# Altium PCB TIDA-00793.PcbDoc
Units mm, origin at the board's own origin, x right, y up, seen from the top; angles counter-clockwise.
Board outline 22.86 x 22.86 mm, 2 copper layers (Top Layer, Bottom Layer), stack 1.575 mm thick; 34 components, 19 nets, 97 pads, 13 vias.
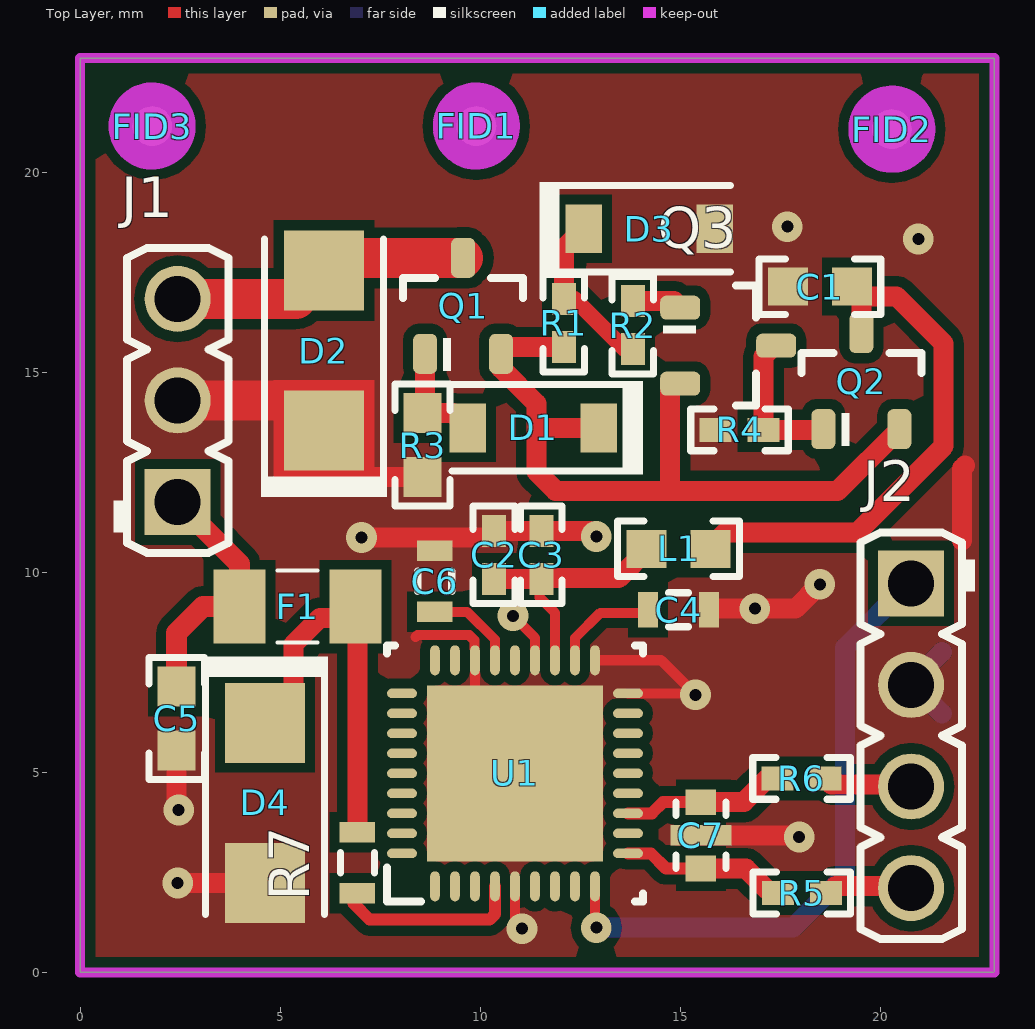
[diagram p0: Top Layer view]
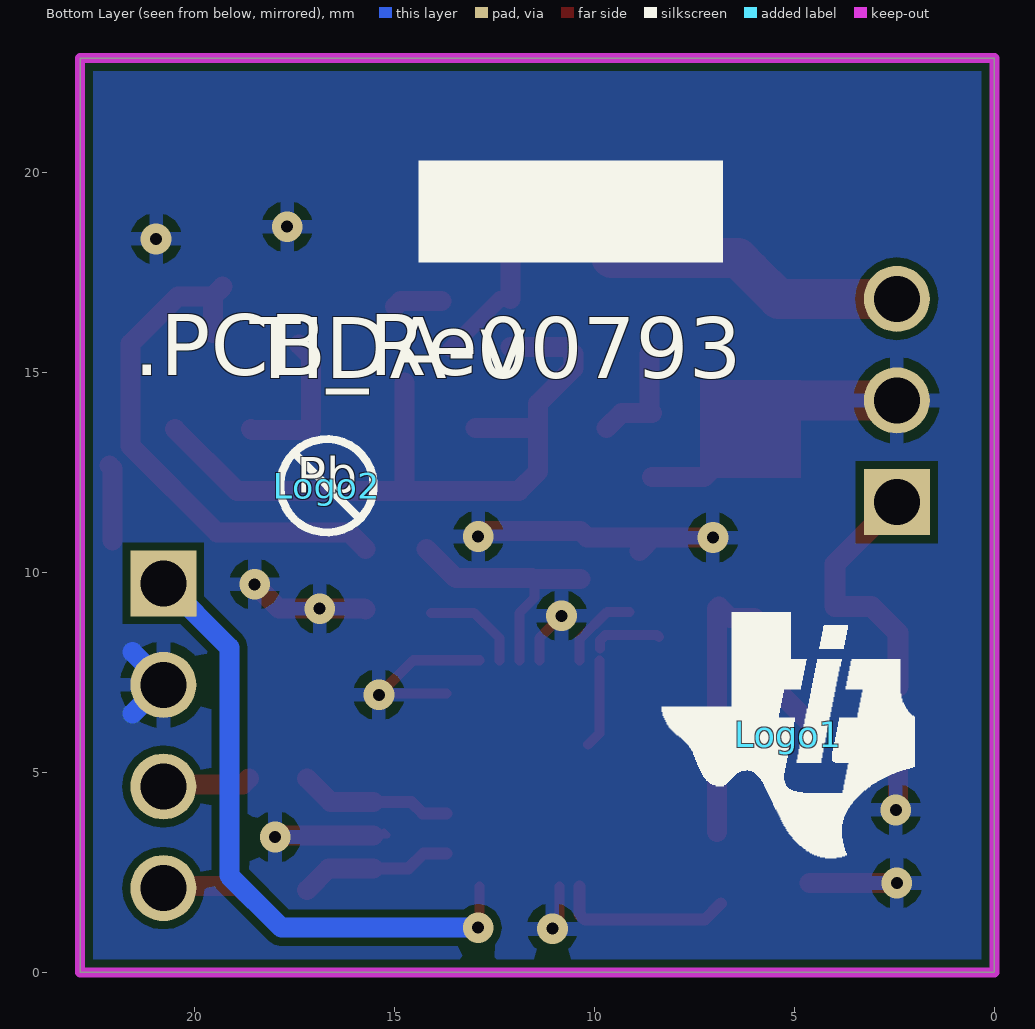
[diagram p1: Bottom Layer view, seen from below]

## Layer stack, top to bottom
Top Solder: solder mask 0.0102, Solder Resist, Dk 3.5
Top Layer: signal copper 0.0356
Dielectric1: core 1.5037, FR-4, Dk 4.8
Bottom Layer: signal copper 0.0356
Bottom Solder: solder mask 0.0102, Solder Resist, Dk 3.5

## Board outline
0,0 22.86,0 22.86,22.86 0,22.86

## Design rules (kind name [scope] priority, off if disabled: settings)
AcuteAngle [All] p1: minimum=4.50000000000000E+0001 checktracksonly=FALSE
AssemblyTestPointUsage [All] p1: valid=2
Clearance Clearance_6 [InNamedPolygon('Top Layer-No Net')] p1: gap=0.254
Clearance Clearance_5 [InNamedPolygon('Bottom Layer-No Net')] p2: gap=0.2
Clearance Clearance_4 [InNamedPolygon('Top Layer-No Net 1')] p3: gap=0.2
Clearance Clearance_3 [InNamedPolygon('Top Layer-No Net 1')] p4: gap=0.254
Clearance Clearance_2 [InNamedPolygon('Top Layer-No Net 1')] p5: gap=0.1
Clearance Clearance_1 [InNamedPolygon('Top Layer-No Net 1')] p6: gap=0.154
Clearance Clearance_Keepouts [((IsTrack Or IsArc) And Not InPoly) And IsFree and IsKeepOut vs ((IsTrack Or IsArc) And Not InPoly) And IsFree and IsKeepOut] p7: gap=0
Clearance Clearance_BoardEdge_MountingHoles [OnCopper and InComponentClass('Mounting Holes') vs IsKeepOut] p8: gap=1.016
Clearance Clearance_BoardEdge_Poly [OnCopper and InPoly vs IsKeepOut] p9: gap=0.635
Clearance Clearance_BoardEdge [OnCopper and Not InComponentClass('Logo') and not InComponentClass('FiducialMark') and not InRegion(1000,500,4000,800) and Not IsKeepout vs IsKeepOut] p10: gap=0.254
Clearance Clearance_Poly [InPolygon vs IsPad] p11: gap=0.1
Clearance [All] p12: gap=0.127
ComponentClearance ComponentClearance_MountingHoles_FiducialMarks [InComponentClass('Mounting Holes') vs InComponentClass('FiducialMark')] p1: gap=1.27 collisioncheckmode=3 verticalgap=0.254 showdistances=FALSE
ComponentClearance ComponentClearance_Shunt [InComponentClass('Header') vs InComponentClass('Shunt')] p2: gap=0 collisioncheckmode=3 verticalgap=0 showdistances=FALSE
ComponentClearance ComponentClearance_Logo [InComponentClass('Logo')] p3: gap=1.27 collisioncheckmode=3 verticalgap=0.254 showdistances=FALSE
ComponentClearance ComponentClearance_ScrewToNut [(HasFootprint('NY PMS 440 0025 PH')) vs (HasFootprint('Keystone_1902C'))] p4: gap=0.127 collisioncheckmode=3 verticalgap=0.254 showdistances=FALSE
ComponentClearance ComponentClearance_MountingHoles [InComponentClass('Mounting Holes')] p5: gap=6.35 collisioncheckmode=3 verticalgap=2540 showdistances=FALSE
ComponentClearance ComponentClearance_SmallPassives [HasFootprint('0201*') or HasFootprint('0402*') or HasFootprint('0508') or HasFootprint('0603*') or HasFootprint('0612') or HasFootprint('0805*') or HasFootprint('0815*') or HasFootprint('0830*') or HasFootprint('1206*') or HasFootprint('1210*') or HasFootprint('1808*') or HasFootprint('1812*') or HasFootprint('1825*') or HasFootprint('2010*') or HasFootprint('2220*') or HasFootprint('2225*') or HasFootprint('2512*') or HasFootprint('2728*') or HasFootprint('3518*') vs HasFootprint('0201*') or HasFootprint('0402*') or HasFootprint('0508') or HasFootprint('0603*') or HasFootprint('0612') or HasFootprint('0805*') or HasFootprint('0815*') or HasFootprint('0830*') or HasFootprint('1206*') or HasFootprint('1210*') or HasFootprint('1808*') or HasFootprint('1812*') or HasFootprint('1825*') or HasFootprint('2010*') or HasFootprint('2220*') or HasFootprint('2225*') or HasFootprint('2512*') or HasFootprint('2728*') or HasFootprint('3518*')] p6: gap=0.508 collisioncheckmode=3 verticalgap=0.254 showdistances=FALSE
ComponentClearance ComponentClearance_THtoSMT [IsThruComponent vs IsSMTComponent] p7: gap=0.5 collisioncheckmode=3 verticalgap=0.762 showdistances=FALSE
ComponentClearance ComponentClearance_THtoTH [IsThruComponent vs IsThruComponent] p8: gap=3 collisioncheckmode=3 verticalgap=0.762 showdistances=FALSE
ComponentClearance [All] p9: gap=0.216 collisioncheckmode=3 verticalgap=0.254 showdistances=FALSE
DiffPairsRouting [All] p1: maxlimit=2.54 minlimit=0.254 mostfreqgap=0.254 toplayer_minwidth=0.381 toplayer_maxwidth=0.381 toplayer_prefwidth=0.381 bottomlayer_minwidth=0.381 bottomlayer_maxwidth=0.381 bottomlayer_prefwidth=0.381 maxuncoupledlength=25.4
FabricationTestPointUsage TestPointUsage [All] p1: valid=2 allowmultiple=FALSE
FabricationTestpoint Testpoint [All] p1: side=3 testpointundercomponent=TRUE minsize=1.016 maxsize=2.54 preferedsize=1.524 minholesize=0 maxholesize=1.016 preferedholesize=0.813 testpointgrid=0.025 allowsidetop=TRUE allowsidebottom=TRUE usegrid=TRUE gridtolerance=0
FanoutControl Fanout_LCC [IsLCC] p1: bgadir=Out bgaviamode=Centered fanoutstyle=Auto fanoutdirection=Alternating viagrid=0.025 // Fanout_LCC (Default Rule)
FanoutControl Fanout_BGA [IsBGA] p2: bgadir=Out bgaviamode=Centered fanoutstyle=Auto fanoutdirection=Alternating viagrid=0.025 // Fanout_BGA (Default Rule)
FanoutControl Fanout_Default [All] p4: bgadir=Out bgaviamode=Centered fanoutstyle=Auto fanoutdirection=Alternating viagrid=0.025 // Fanout_Default (Default Rule)
FanoutControl Fanout_Small [(CompPinCount < 5)] p5: bgadir=Out bgaviamode=Centered fanoutstyle=Auto fanoutdirection=OutThenIn viagrid=0.025 // Fanout_Small (Default Rule)
HoleSize [All] p1: absolutevalues=TRUE maxlimit=6.375 minlimit=0.2 maxpercent=80.000 minpercent=20.000
MinimumAnnularRing MinimumAnnularRing_ThermalPadVias [IsVia and InAnyComponent] p1: minimumring=0.15
MinimumAnnularRing [All] p2: minimumring=0.229
MinimumSolderMaskSliver MinimumSolderMaskSliver_Logo [InComponentClass('Logo') vs InComponentClass('Logo')] p1: minsoldermaskwidth=0.018
MinimumSolderMaskSliver [All] p2: minsoldermaskwidth=0.01
PlaneClearance [All] p1: clearance=0.308
PlaneConnect [All] p1: planeconnectstyle=Relief reliefexpansion=0.254 reliefentries=4 reliefconductorwidth=0.254 reliefairgap=0.154
PolygonConnect PolygonConnect_3 [All vs IsNamedPolygon('Bottom Layer-No Net')] p1: connectstyle=Relief reliefconductorwidth=0.354 reliefentries=4 polygonreliefangle="90 Angle" airgapwidth=0.254
PolygonConnect PolygonConnect_2 [All vs IsNamedPolygon('Bottom Layer-No Net')] p2: connectstyle=Relief reliefconductorwidth=0.354 reliefentries=4 polygonreliefangle="90 Angle" airgapwidth=0.254
PolygonConnect PolygonConnect_1 [All vs IsNamedPolygon('Top Layer-No Net')] p3: connectstyle=Direct reliefconductorwidth=0.254 reliefentries=4 polygonreliefangle="90 Angle" airgapwidth=0.254
PolygonConnect [All] p4: connectstyle=Relief reliefconductorwidth=0.354 reliefentries=4 polygonreliefangle="90 Angle" airgapwidth=0.254
RoutingVias ThermalPadVias [IsVia and InAnyComponent] p1: holewidth=0.2 width=0.5 viastyle="Through Hole" minholewidth=0.2 minwidth=0.5 maxholewidth=0.33 maxwidth=0.6
RoutingVias [All] p2: holewidth=0.406 width=0.864 viastyle="Through Hole" minholewidth=0.2 minwidth=0.66 maxholewidth=1.016 maxwidth=1.651
SilkToBoardRegionClearance [Not ((IsComment or IsDesignator) And (Hide <> 'False')) and not InRegion(1000,500,4000,800)] p1:
SilkToSilkClearance SilkToSilkClearance_Pb-FreeLogo [(HasFootprint('Pb-Free_Overlay_Medium') OR HasFootprint('Pb-Free_Overlay_Small')) vs (HasFootprint('Pb-Free_Overlay_Medium') OR HasFootprint('Pb-Free_Overlay_Small'))] p1: silktosilkclearance=0
SilkToSilkClearance [All] p2: silktosilkclearance=0
SilkToSolderMaskClearance SilkToComonentPadClearance [IsPad and InAnycomponent] p1: minsilkscreentomaskgap=0 clearancetoexposedcopper=TRUE
SilkToSolderMaskClearance "Silk to Solder Mask Opening" [All] p2 off: minsilkscreentomaskgap=0 clearancetoexposedcopper=FALSE
SolderMaskExpansion [All] p1: expansion=0.05
UnpouredPolygon [All] p1: allowunpoured=FALSE
Width [All] p1: maxlimit=2.54 minlimit=0.152 preferedwidth=0.254 checkconnectedcopper=TRUE
13 further rules are at their usual default settings.

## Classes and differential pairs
component class Header: J1 J2
component class Logo: Logo1
component class TIDA-00793_Hardware: FID1 FID2 FID3 Logo1 Logo2 ZZ1 ZZ2 ZZ3
component class FiducialMark: FID1 FID2 FID3
component class AssemblyNote: ZZ1 ZZ2 ZZ3
component class TIDA-00793_PressureSensorSchematic: C1 C2 C3 C4 C5 C6 C7 D1 D2 D3 D4 F1 J1 J2 L1 PGA301 Q1 Q2 Q3 R1 R2 R3 R4 R5 R6 R7 U1

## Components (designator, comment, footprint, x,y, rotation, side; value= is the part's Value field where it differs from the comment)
C1 "GRM188Z71C225KE43" 0603 18.494,17.145 r180 top
C2 "GRM155R71C153JA01D" 0402 10.349,10.439 r90 top
C3 "GRM155R71C104JA88D" 0402 11.532,10.439 r90 top
C4 "0603YC104JAT2A" 0603S 14.963,9.068 r180 top
C5 "C0603C680J5GACTU" 0603 2.416,6.35 r270 top
C6 "0603YC104JAT2A" 0603S 8.867,9.779 r270 top
C7 "500X14W103MV4T" X2Y_0603 15.522,3.429 r270 top
D1 "MMSZ5232B-7-F" SOD-123 11.331,13.614 r180 top
D2 "SM4T23CAY" SMA 6.099,15.545 r90 top
D3 "MMSZ5232B-7-F" SOD-123 14.227,18.593 r0 top
D4 "1SMA5922BT3G" SMA 4.625,4.242 r270 top
F1 "NANOSMDC020F-2" FUSE_NANO02 5.438,9.144 r0 top
FID1 "Fiducial" Fiducial10-20 9.906,21.158 r0 top
FID2 "Fiducial" Fiducial10-20 20.295,21.082 r0 top
FID3 "Fiducial" Fiducial10-20 1.803,21.158 r0 top
J1 "61300311121" WURTH_61300311121 2.441,14.3 r90 top
J2 "61300411121" WURTH_61300411121 20.777,5.918 r270 top
L1 "74279266" 0603 14.963,10.592 r180 top
Logo1 "Texas Instruments" TI_Symbol_Overlay_Medium 5.156,5.944 r180 bottom
Logo2 "Pb-Free Symbol" Pb-Free_Overlay_Small 16.688,12.167 r180 bottom
Q1 "DMP3098L-7" SOT-23 9.578,16.662 r90 top
Q2 "FMMT720TA" SOT-23 19.535,14.783 r90 top
Q3 "BC857C-7-F" SOT-23 16.205,15.672 r0 top
R1 "CRCW04022K74FKED" 0402 12.093,16.231 r270 top
R2 "CRCW04026K81FKED" 0402 13.82,16.18 r90 top
R3 "CRCW060320K0FKEA" 0603 8.562,13.183 r90 top
R4 "CRCW04026K81FKED" 0402 16.487,13.564 r0 top
R5 "CRCW040249R9FKED" 0402 18.045,1.986 r180 top
R6 "CRCW040249R9FKED" 0402 18.037,4.851 r180 top
R7 "MCR03EZPJ000" 0603S 6.934,2.743 r90 top
U1 "PGA301RHHQ1" RHH0036C_NV 10.874,4.978 r90 top
ZZ1 "These assemblies are ESD sensitive, ESD precautions shall be observed." AssemblyNote 3.251,37.29 r0 top
ZZ2 "These assemblies must be clean and free from flux and all contaminants. Use of no clean flux is not acceptable." AssemblyNote 3.251,35.041 r0 top
ZZ3 "These assemblies must comply with workmanship standards IPC-A-610 Class 2, unless otherwise specified." AssemblyNote 3.251,32.791 r0 top

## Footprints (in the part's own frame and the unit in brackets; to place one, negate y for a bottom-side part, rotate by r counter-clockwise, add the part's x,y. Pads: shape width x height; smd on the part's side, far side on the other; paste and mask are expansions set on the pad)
0402 [mm] "0402 from SM-752 data"
  rect 0.8x0.6 smd: 1(-0.6,0) 2(0.6,0)
  silkscreen extent -1.22,-0.52 1.22,0.52, body extent -0.55,-0.3 0.55,0.3, height 0.6
0603 [mm] "0603 from SM-752 data"
  rect 1x0.95 smd: 1(-0.8,0) 2(0.8,0)
  silkscreen extent -1.52,-0.69 1.52,0.69, body extent -0.87,-0.47 0.87,0.47, height 1
0603S [mil]
  rect 20x35 smd: 1(-30,0) 2(30,0)
  silkscreen extent -10,-17 10,17, body extent -34,-19 34,19, height 39
AssemblyNote [mm] "Assembly Note"
Fiducial10-20 [mm]
  round 1 smd mask+0.5: 1(0,0)
  Top Layer keep-out circle w1.178: c0,0 r0.5
FUSE_NANO02 [mm] "SMD, Body 3.2x1.585mm"
  rect 1.3x1.85 smd: 1(-1.45,0) 2(1.45,0)
  silkscreen extent -0.5,-0.9 0.5,0.9, body extent -1.7,-0.9 1.7,0.9, height 0.82
Pb-Free_Overlay_Small [mm]
  silkscreen extent -1.17,-1.17 1.16,1.17
RHH0036C_NV [mm] "QFN, 36-Leads, Body 6x6mm, Pitch 0.5mm, Thermal Pad 4.4x4.4mm, TI Recommended"
  oval 0.75x0.24 smd: 1(-2.825,2) 2(-2.825,1.5) 3(-2.825,1) 4(-2.825,0.5) 5(-2.825,0) 6(-2.825,-0.5) 7(-2.825,-1) 8(-2.825,-1.5) 9(-2.825,-2) 19(2.825,-2) 20(2.825,-1.5) 21(2.825,-1) 22(2.825,-0.5) 23(2.825,0) 24(2.825,0.5) 25(2.825,1) 26(2.825,1.5) 27(2.825,2)
  oval 0.24x0.75 smd: 10(-2,-2.825) 11(-1.5,-2.825) 12(-1,-2.825) 13(-0.5,-2.825) 14(0,-2.825) 15(0.5,-2.825) 16(1,-2.825) 17(1.5,-2.825) 18(2,-2.825) 28(2,2.825) 29(1.5,2.825) 30(1,2.825) 31(0.5,2.825) 32(0,2.825) 33(-0.5,2.825) 34(-1,2.825) 35(-1.5,2.825) 36(-2,2.825)
  rect 4.4x4.4 smd paste-2.2: 37(0,0)
  silkscreen extent -3.2,-3.2 3.2,3.2, body extent -3.05,-3.05 3.05,3.05, height 1.01
SMA [mm] "Molded Diode, 2-Leads, Body 4.3x2.6mm, IPC Medium Density, based on OnSemi component dimensions and land pattern"
  rect 2x2 smd: 1(-2,0) 2(2,0)
  silkscreen extent -3.66,-1.57 2.79,1.57, body extent -2.6,-1.3 2.6,1.3, height 2.42
SOD-123 [mm] "On Semi recommended land pattern"
  rect 0.915x1.22 smd: 1(-1.637,0) 2(1.637,0)
  silkscreen extent -2.74,-1.17 2.03,1.17, body extent -1.93,-0.9 1.93,0.9, height 1.35
SOT-23 [mm] "SOT23, 3-Leads, Body 2.9x1.3mm, Pitch 0.95mm, Lead Span 2.5mm, IPC Medium Density"
  rrect50% 1x0.6 smd: 1(-1.2,0.95) 2(-1.2,-0.95) 3(1.2,0)
  silkscreen extent -1.62,-1.5 0.7,1.5, body extent -1.16,-1.45 1.21,1.45, height 1
TI_Symbol_Overlay_Medium [mm]
  silkscreen extent -3.16,-3.09 3.16,3.06
WURTH_61300311121 [mm] "Header, 2.54mm, 3x1, TH"
  rect 1.65x1.65 hole 1.15: 1(-2.54,0)
  round 1.65 hole 1.15: 2(0,0) 3(2.54,0)
  silkscreen extent -3.81,-1.27 3.81,1.6, body extent -3.81,-1.27 3.81,1.27, height 8.54
WURTH_61300411121 [mm] "Header, 2.54mm, 4x1, TH"
  rect 1.65x1.65 hole 1.15: 1(-3.81,0)
  round 1.65 hole 1.15: 2(-1.27,0) 3(1.27,0) 4(3.81,0)
  silkscreen extent -5.08,-1.27 5.08,1.6, body extent -5.08,-1.27 5.08,1.27, height 8.54
X2Y_0603 [mm] "0402 from SM-752 data"
  rect 0.64x0.76 smd: 1(-0.83,0) 2(0.83,0)
  rect 0.51x1.52 smd: 3(0,0)
  silkscreen extent -0.82,-0.63 0.82,0.63, body extent -0.88,-0.51 0.88,0.51, height 0.75

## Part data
C1: "CAP, CERM, 2.2 µF, 16 V, +/- 10%, X7R, 0603"
C2: "CAP, CERM, 0.015 µF, 16 V, +/- 5%, X7R, 0402"
C3: "CAP, CERM, 0.1 µF, 16 V, +/- 5%, X7R, 0402"
C4 C6: "CAP, CERM, 0.1 µF, 16 V, +/- 5%, X7R, 0603"
C5: "CAP, CERM, 68 pF, 50 V, +/- 5%, C0G/NP0, 0603"
C7: "CAP, CERM, 0.01 µF, 50 V, +/- 20%, X7R, 0603"
D1 D3: "Diode, Zener, 5.6 V, 500 mW, SOD-123"
D2: library part SM4T23AY/CAY, "Diode, TVS, Bi, 20 V, 400 W, AEC-Q101, SMA"
D4: "Diode, Zener, 7.5 V, 1.5 W, AEC-Q101, SMA"
F1: "Fuse, Resettable, 0.2 A, 24 V, SMD"
FID1 FID2 FID3: "Fiducial mark.  There is nothing to buy or mount."
J1: "Header, 2.54 mm, 3x1, Gold, TH"
J2: "Header, 2.54 mm, 4x1, Gold, TH"
L1: "Ferrite Bead, 1000 ohm @ 100 MHz, 0.2 A, 0603"
Logo1: library part TI_Logo, "Texas Instrument Corporate Signature"
Logo2: library part Pb-Free
Q1: "MOSFET, P-CH, -30 V, -3.8 A, AEC-Q101, SOT-23"
Q2: library part "FMMT720TA, Diodes Inc.", "Transistor, PNP, 40 V, 1.5 A, AEC-Q101, SOT-23"
Q3: library part "BC857C-7-F, Diodes Inc.", "Transistor, PNP, 45 V, 0.1 A, SOT-23"
R1: "RES, 2.74 k, 1%, 0.063 W, 0402"
R2 R4: "RES, 6.81 k, 1%, 0.063 W, 0402"
R3: "RES, 20.0 k, 1%, 0.1 W, 0603"
R5 R6: "RES, 49.9, 1%, 0.063 W, 0402"
R7: "RES, 0, 5%, 0.1 W, 0603"
U1: "Resistive Bridge Sensor Signal Conditioner for Automotive application, RHH0036C"
ZZ1 ZZ2 ZZ3: library part AssemblyNote

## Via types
v1: diameter 0.77, hole 0.3, Top Layer to Bottom Layer, 13 vias

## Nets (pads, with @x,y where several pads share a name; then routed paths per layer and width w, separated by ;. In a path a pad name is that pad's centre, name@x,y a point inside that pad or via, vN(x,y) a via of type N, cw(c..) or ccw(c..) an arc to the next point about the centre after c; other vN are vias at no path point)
+5V: D2.2 J1.3 Q1.3 | length 7.6
  Top Layer w1: J1.3 5.394,16.84 D2.2 6.416,17.862 Q1.3
GND: C1.2 C2.2 C3.2 C4.1 C5.2 C6.1 C7.3 D2.1 D3.2 D4.2 J1.2 J2.2 R3.1 R4.1 U1.5 U1.18 U1.19 U1.22 U1.25 U1.37 | length 38.2
  Top Layer w0.156: C7.3 C7.3@15.268,3.429 ; C7.3@15.268,3.429 15.268,3.525 15.172,3.429 C7.3@15.268,3.429
  Top Layer w0.25: 8.382,8.382 8.43,8.43 9.731,8.43 9.856,8.306 U1.25@9.856,8.103 ; U1.25 9.874,5.978 U1.37@10.159,5.693 ; v1(10.823,8.915) 11.374,8.365 U1.22 ; U1.5 10.874,1.27 v1(11.052,1.092) ; U1.18 v1@15.352,6.978
  Top Layer w0.254: U1.19 14.527,7.803 v1@15.352,6.978
  Top Layer w0.5: C5.2 2.416,4.115 v1(2.466,4.064) ; v1(2.441,2.235) 4.619,2.235 D4.2 ; D2.1 7.261,12.383 R3.1 ; v1(7.038,10.871) 8.537,10.871 ; C6.1 8.537,10.871 ; v1(12.906,10.897) 12.763,11.039 11.492,11.039 C2.2 10.181,10.871 8.537,10.871 ; C7.3 17.936,3.429 v1(17.98,3.385) ; C4.1 15.751,9.093 v1(16.868,9.093) 17.884,9.093 v1(18.494,9.703) ; 22.05,10.799 22.05,12.601 22.123,12.675
  Top Layer w1: J1.2 5.343,14.3 D2.1
  Bottom Layer w0.5: 21.549,6.469 20.78,7.239 21.549,8.009
  other v1: 15.389,6.941 20.958,18.339 17.681,18.644
NetC2_1: C2.1 C3.1 L1.2 U1.21 | length 6.3
  Top Layer w0.25: C3.1@11.492,9.839 11.492,9.373 11.874,8.991 U1.21
  Top Layer w0.3: C2.1@10.34,9.83 C2.1
  Top Layer w0.5: C2.1 C3.1@11.492,9.839 ; C3.1@11.56,9.855 13.465,9.855 L1.2@14.201,10.592
NetC4_2: C4.2 U1.20 | length 2.5
  Top Layer w0.25: U1.20 12.374,8.358 13.007,8.992 C4.2@14.089,8.992
NetC6_2: C6.2 U1.24 | length 2.1
  Top Layer w0.25: C6.2@9.121,9.017 9.677,9.017 10.374,8.321 U1.24
NetC7_1: C7.1 R6.2 U1.12 | length 3.9
  Top Layer w0.3: U1.12 14.293,3.978 14.574,4.259 C7.1
  Top Layer w0.5: C7.1 16.595,4.259 R6.2@17.188,4.851
NetC7_2: C7.2 R5.2 U1.10 | length 3.9
  Top Layer w0.3: U1.10 14.271,2.978 14.65,2.599 C7.2
  Top Layer w0.5: C7.2 16.646,2.599 R5.2@17.188,2.057
NetD1_1: D1.1 Q1.2 Q2.2 Q3.2 R1.2 | length 19.2
  Top Layer w0.5: R1.2 10.697,15.631 Q1.2 10.528,15.103 11.407,14.224 11.407,13.64 ; D1.1 11.433,13.614 11.407,13.64 ; Q3.2@14.754,14.747 14.754,12.097 14.811,12.04 ; Q2.2 18.942,12.04 14.811,12.04 ; 11.407,13.64 11.407,12.522 11.89,12.04 14.811,12.04
NetD1_2: D1.2 Q1.1 R3.2 | length 2.7
  Top Layer w0.5: R3.2 9.325,13.983 D1.2 ; R3.2@8.628,14.049 Q1.1
NetD3_1: D3.1 R1.1 R2.1 | length 4
  Top Layer w0.4: R1.1 12.366,16.831 R2.1@13.617,15.58
  Top Layer w0.5: R1.1 12.093,18.097 D3.1
NetD4_1: D4.1 F1.2 R7.2 | length 9.9
  Top Layer w0.5: D4.1 5.337,6.953 5.337,8.204 5.997,8.865 6.609,8.865 F1.2 6.937,9.095 6.937,6.274 R7.2@6.937,3.505
NetJ2_1: J2.1 U1.9 | length 15.9
  Top Layer w0.25: v1@12.874,1.15 U1.9
  Top Layer w0.3: v1@12.874,1.15 v1(12.906,1.118)
  Bottom Layer w0.5: v1(12.906,1.118) 17.826,1.118 19.126,2.418 19.126,8.125 J2.1@20.78,9.779
NetQ2_1: Q2.1 Q3.3 R4.2 | length 3.8
  Top Layer w0.5: Q3.3@17.382,15.697 17.087,15.402 R4.2 18.566,13.564 Q2.1
NetQ3_1: Q3.1 R2.2 | length 1.2
  Top Layer w0.5: R2.2 14.85,16.78 Q3.1@14.982,16.647
NetR7_1: R7.1 U1.4 | length 4.5
  Top Layer w0.3: R7.1@6.835,1.727 7.242,1.321 10.239,1.321 10.374,1.456 U1.4
OUTPUT: C5.1 F1.1 J1.1 | length 6.4
  Top Layer w0.524: C5.1 2.416,8.484 3.076,9.144 F1.1 3.988,10.213 J1.1
VCC: C1.1 L1.1 Q2.3 | length 13.3
  Top Layer w0.5: L1.1@15.725,10.592 16.132,10.998 19.434,10.998 21.593,13.157 21.593,15.723 20.412,16.904 C1.1@19.535,16.904 ; C1.1 C1.1@19.535,16.904 ; Q2.3 C1.1@19.535,16.904
"VIN1 BRIDGE": J2.4 R5.1 | length 2.2
  Top Layer w0.5: R5.1@18.687,1.956 18.891,2.159 J2.4@20.78,2.159
"VIN2 BRIDGE": J2.3 R6.1 | length 2.2
  Top Layer w0.5: R6.1 18.789,4.699 J2.3@20.78,4.699
pads on no net: FID1.1 FID2.1 FID3.1 U1.1 U1.2 U1.3 U1.6 U1.7 U1.8 U1.11 U1.13 U1.14 U1.15 U1.16 U1.17 U1.23 U1.26 U1.27 U1.28 U1.29 U1.30 U1.31 U1.32 U1.33 U1.34 U1.35 U1.36

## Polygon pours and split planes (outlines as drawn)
GND on Bottom Layer "Bottom Layer-No Net" (solid, remove dead copper, pour order 4): 0,22.784 22.86,22.784 22.86,0 0,0
GND on Top Layer "Top Layer-No Net" (solid, remove dead copper, pour order 3): 0.203,22.86 22.86,22.86 22.86,0 0,0

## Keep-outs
Keep-Out Layer:
  lines w0.025: 331.529,173.744 334.061,176.276 337.109,179.324 340.157,182.372 343.205,185.42 346.253,188.468 349.301,191.516 352.349,194.564 ; 331.529,175.268 332.537,176.276 335.585,179.324 338.633,182.372 341.681,185.42 344.729,188.468 347.777,191.516 350.825,194.564 ; 331.529,176.792 334.061,179.324 337.109,182.372 340.157,185.42 343.205,188.468 346.253,191.516 349.301,194.564 ; 331.529,178.316 332.537,179.324 335.585,182.372 338.633,185.42 341.681,188.468 344.729,191.516 347.777,194.564 ; 331.529,179.84 334.061,182.372 337.109,185.42 340.157,188.468 343.205,191.516 346.253,194.564 ; 331.529,181.364 332.537,182.372 335.585,185.42 338.633,188.468 341.681,191.516 344.729,194.564 ; 331.529,182.888 334.061,185.42 337.109,188.468 340.157,191.516 343.205,194.564 ; 331.529,184.412 332.537,185.42 335.585,188.468 338.633,191.516 341.681,194.564 ; 331.529,185.936 334.061,188.468 337.109,191.516 340.157,194.564 ; 331.529,187.46 332.537,188.468 335.585,191.516 338.633,194.564 ; 331.529,188.984 334.061,191.516 337.109,194.564 ; 331.529,190.508 332.537,191.516 335.585,194.564 ; 331.529,192.032 334.061,194.564 ; 331.529,193.556 332.537,194.564 ; 332.537,173.228 335.585,176.276 338.633,179.324 341.681,182.372 344.729,185.42 347.777,188.468 350.825,191.516 353.873,194.564 ; 334.061,173.228 337.109,176.276 340.157,179.324 343.205,182.372 346.253,185.42 349.301,188.468 352.349,191.516 355.397,194.564 ; 335.585,173.228 338.633,176.276 341.681,179.324 344.729,182.372 347.777,185.42 350.825,188.468 353.873,191.516 356.921,194.564 ; 337.109,173.228 340.157,176.276 343.205,179.324 346.253,182.372 349.301,185.42 352.349,188.468 355.397,191.516 358.445,194.564 ; 338.633,173.228 341.681,176.276 344.729,179.324 347.777,182.372 350.825,185.42 353.873,188.468 356.921,191.516 359.969,194.564 ; 340.157,173.228 343.205,176.276 346.253,179.324 349.301,182.372 352.349,185.42 355.397,188.468 358.445,191.516 359.969,193.04 ; 341.681,173.228 344.729,176.276 347.777,179.324 350.825,182.372 353.873,185.42 356.921,188.468 359.969,191.516 ; 343.205,173.228 346.253,176.276 349.301,179.324 352.349,182.372 355.397,185.42 358.445,188.468 359.969,189.992 ; 344.729,173.228 347.777,176.276 350.825,179.324 353.873,182.372 356.921,185.42 359.969,188.468 ; 346.253,173.228 349.301,176.276 352.349,179.324 355.397,182.372 358.445,185.42 359.969,186.944 ; 347.777,173.228 350.825,176.276 353.873,179.324 356.921,182.372 359.969,185.42 ; 349.301,173.228 352.349,176.276 355.397,179.324 358.445,182.372 359.969,183.896 ; 350.825,173.228 353.873,176.276 356.921,179.324 359.969,182.372 ; 352.349,173.228 355.397,176.276 358.445,179.324 359.969,180.848 ; 353.873,173.228 356.921,176.276 359.969,179.324 ; 355.397,173.228 358.445,176.276 359.969,177.8 ; 356.921,173.228 359.969,176.276 ; 358.445,173.228 359.969,174.752
  lines w0.254: 0,0 22.86,0 22.86,22.86 0,22.86 0,0
  lines w0.381: 244.683,176.276 255.095,176.276 278.71,176.276 300.549,176.276 317.054,176.276 331.529,176.276 359.969,176.276 ; 244.683,179.324 255.095,179.324 278.71,179.324 300.549,179.324 317.054,179.324 331.529,179.324 359.969,179.324 ; 244.683,182.372 255.095,182.372 278.71,182.372 300.549,182.372 317.054,182.372 331.529,182.372 359.969,182.372 ; 244.683,185.42 255.095,185.42 278.71,185.42 300.549,185.42 317.054,185.42 331.529,185.42 359.969,185.42 ; 244.683,188.468 255.095,188.468 278.71,188.468 300.549,188.468 317.054,188.468 331.529,188.468 359.969,188.468 ; 244.683,191.516 255.095,191.516 278.71,191.516 300.549,191.516 317.054,191.516 331.529,191.516 359.969,191.516 ; 244.683,194.564 359.969,194.564 ; 255.095,197.612 255.095,173.228 ; 278.71,197.612 278.71,173.228 ; 300.549,197.612 300.549,173.228 ; 317.054,197.612 317.054,173.228 ; 331.529,197.612 331.529,173.228 ; 255.095,173.228 278.71,173.228 ; 255.095,173.228 244.683,173.228 244.683,197.612 359.969,197.612 359.969,173.228 331.529,173.228 ; 278.71,173.228 300.549,173.228 ; 300.549,173.228 317.054,173.228 ; 317.054,173.228 331.529,173.228
  text "Layer" at 246.207,195.326 h1.52
  text "Name" at 256.619,195.326 h1.52
  text "Material" at 280.234,195.326 h1.52
  text "Thickness" at 302.073,195.326 h1.52
  text "Constant" at 318.578,195.326 h1.52
  text "Board Layer Stack" at 333.053,195.326 h1.52
  text "1" at 246.207,192.278 h1.52
  text "Top Overlay" at 256.619,192.278 h1.52
  text "2" at 246.207,189.23 h1.52
  text "Top Solder" at 256.619,189.23 h1.52
  text "Solder Resist" at 280.234,189.23 h1.52
  text "0.40mil" at 302.073,189.23 h1.52
  text "3.5" at 318.578,189.23 h1.52
  text "3" at 246.207,186.182 h1.52
  text "Top Layer" at 256.619,186.182 h1.52
  text "Copper" at 280.234,186.182 h1.52
  text "1.40mil" at 302.073,186.182 h1.52
  text "4" at 246.207,183.134 h1.52
  text "Dielectric1" at 256.619,183.134 h1.52
  text "FR-4" at 280.234,183.134 h1.52
  text "59.20mil" at 302.073,183.134 h1.52
  text "4.8" at 318.578,183.134 h1.52
  text "5" at 246.207,180.086 h1.52
  text "Bottom Layer" at 256.619,180.086 h1.52
  text "Copper" at 280.234,180.086 h1.52
  text "1.40mil" at 302.073,180.086 h1.52
  text "6" at 246.207,177.038 h1.52
  text "Bottom Solder" at 256.619,177.038 h1.52
  text "Solder Resist" at 280.234,177.038 h1.52
  text "0.40mil" at 302.073,177.038 h1.52
  text "3.5" at 318.578,177.038 h1.52
  text "7" at 246.207,173.99 h1.52
  text "Bottom Overlay" at 256.619,173.99 h1.52
  text ".Layer_Name" at 14.656,-21.806 h1.52

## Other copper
Top Layer:
  region net GND: 4.845,12.37 4.845,14.799 7.353,14.799 7.353,12.37
  text ".Layer_Name" at 14.656,-21.806 h1.52
Bottom Layer:
  text ".Layer_Name" at 14.656,-21.806 h1.52

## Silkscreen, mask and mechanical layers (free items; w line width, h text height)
Top Overlay:
  text ".Layer_Name" at 14.656,-21.806 h1.52
Bottom Overlay:
  rectangle: 6.782,17.755 14.402,20.295
  text ".PCB_Rev" at 21.514,14.935 h1.52
  text "TIDA-00793" at 18.618,14.859 h1.52
  text ".Layer_Name" at 14.656,-21.806 h1.52
Top Paste:
  text ".Layer_Name" at 14.656,-21.806 h1.52
Bottom Paste:
  text ".Layer_Name" at 14.656,-21.806 h1.52
Top Solder:
  text ".Layer_Name" at 14.656,-21.806 h1.52
  text ".Layer_Name" at 14.656,-21.806 h1.52
Bottom Solder:
  text ".Layer_Name" at 14.656,-21.806 h1.52
Drill Guide:
  text ".Layer_Name" at 14.656,-21.806 h1.52
M1 Board Outline:
  the board outline again, w0.254
  text ".Layer_Name" at 14.656,-21.806 h1.52
M2 Board Dimensions:
  rectangle: 0,-6.985 3.175,-3.81
  rectangle: 3.175,-10.16 12.7,-6.985
  lines w0.178: 0,-6.985 25.4,-6.985 ; 3.175,-10.16 3.175,-3.81 ; 6.35,-10.16 6.35,-3.81 ; 12.7,-10.16 12.7,-3.81 ; 19.05,-10.16 19.05,-3.81 ; 0,-10.16 25.4,-10.16 25.4,-3.81 0,-3.81 0,-10.16
  text ".Layer_Name" at 14.656,-21.806 h1.52
M3 3D STEP Top:
  text ".Layer_Name" at 14.656,-21.806 h1.52
M4 3D STEP Bottom:
  text ".Layer_Name" at 14.656,-21.806 h1.52
M5 Assembly Top:
  lines w0.254: -7.417,-23.626 160.223,-23.626 ; -7.417,-18.462 160.274,-18.462 ; -7.417,-13.297 -7.417,-28.791 94.31,-28.791 160.274,-28.791 160.274,-13.297 -7.404,-13.297 -7.404,-28.791 32.614,-28.791 ; 55.194,-28.791 55.194,-13.297 ; 87.376,-18.462 87.376,-13.297 ; 108.712,-18.462 108.712,-13.297 ; 124.511,-28.956 124.511,-23.804
  text "COMPONENTS MARKED 'DNP' SHOULD NOT BE POPULATED." at 29.299,-8.09 h1.52
  text "ASSEMBLY VARIANT:" at 29.286,-11.024 h1.52
  text ".VariantName" at 55.601,-11.024 h1.52
  text "PCB VIEWED FROM TOP SIDE" at -5.804,-16.654 h1.52
  text "BOARD #:" at 57.099,-16.654 h1.52
  text ".PRJ_Number" at 70.955,-16.654 h1.52
  text "REV:" at 92.405,-16.654 h1.52
  text ".PCB_Rev" at 99.809,-16.654 h1.52
  text "SVN REV:" at 113.69,-16.654 h1.52
  text ".VersionControl_RevNumber" at 126.543,-16.654 h1.52
  text "TID #:" at 57.099,-21.819 h1.52
  text ".TID" at 70.955,-21.819 h1.52
  text "PLOT NAME =" at -5.804,-27.034 h1.52
  text ".plot_File_Name" at 14.656,-27.034 h1.52
  text "GENERATED    :" at 57.15,-27.034 h1.52
  text ".Print_Date" at 79.235,-27.034 h1.52
  text ".Print_Time" at 97.752,-27.034 h1.52
  text "TEXAS INSTRUMENTS" at 129.87,-27.034 h1.52
M6 Assembly Bottom:
  lines w0.254: -7.429,-18.474 160.261,-18.474 ; -7.379,-23.639 160.261,-23.639 ; 28.334,-28.969 28.334,-23.817 ; 44.133,-18.474 44.133,-13.31 ; 65.468,-18.474 65.468,-13.31 ; 97.65,-28.804 97.65,-13.31 ; 120.231,-28.804 160.249,-28.804 160.249,-13.31 -7.429,-13.31 -7.429,-28.804 58.534,-28.804 160.261,-28.804 160.261,-13.31
  text "ASSEMBLY VARIANT:" at 154.864,-11.024 h1.52
  text ".VersionControl_RevNumber" at 26.302,-16.667 h1.52
  text "SVN REV:" at 39.154,-16.667 h1.52
  text ".PCB_Rev" at 53.035,-16.667 h1.52
  text "REV:" at 60.439,-16.667 h1.52
  text ".PRJ_Number" at 81.89,-16.667 h1.52
  text "BOARD #:" at 95.745,-16.667 h1.52
  text "PCB VIEWED FROM BOTTOM SIDE" at 158.648,-16.667 h1.52
  text ".TID" at 81.89,-21.831 h1.52
  text "TID #:" at 95.745,-21.831 h1.52
  text "TEXAS INSTRUMENTS" at 22.974,-27.047 h1.52
  text ".Print_Time" at 55.093,-27.047 h1.52
  text ".Print_Date" at 73.609,-27.047 h1.52
  text "GENERATED    :" at 95.694,-27.047 h1.52
  text ".plot_File_Name" at 138.189,-27.047 h1.52
  text "PLOT NAME =" at 158.648,-27.047 h1.52
M9 Title Sheet:
  drawing of 57 lines, arcs and shapes, not listed
  text "1" at 18.792,204.127 h1.78
  text "2" at 82.182,204.127 h1.78
  text "3" at 145.411,204.127 h1.78
  text "4" at 209.08,204.127 h1.78
  text "5" at 272.555,204.127 h1.78
  text "6" at 336.182,204.127 h1.78
  text "A" at -10.579,175.095 h1.78
  text "A" at 365.341,175.095 h1.78
  text "B" at -10.579,114.643 h1.78
  text "B" at 365.341,114.643 h1.78
  text "C" at -10.579,54.318 h1.78
  text "C" at 365.341,54.318 h1.78
  text "PROJECT TITLE:" at 288.125,7.048 h1.14
  text ".PRJ_Title" at 289.395,3.662 h1.78
  text "DESIGNED FOR:" at 288.125,-0.597 h1.14
  text ".PRJ_Customer" at 289.395,-4.153 h1.78
  text "D" at -10.579,-5.88 h1.78
  text "D" at 365.341,-5.88 h1.78
  text "FILE NAME:" at 288.125,-8.217 h1.14
  text ".PCB_File_Name_No_Path" at 289.395,-11.265 h1.78
  text "Texas Instruments (TI) and/or its licensors do not warrant the accuracy or completeness of this specification" at 161.9,-15.376 h1.14
  text "ENGINEER:" at 288.125,-15.583 h1.14
  text "LAYOUT BY:" at 326.352,-15.583 h1.14
  text "or any information contained therein. TI and/or its licensors do not warrant that this design will meet" at 160.757,-18.237 h1.14
  text ".PRJ_Engineer" at 289.395,-19.52 h1.78
  text ".PCB_Layout" at 327.635,-19.52 h1.78
  text "the specifications, will be suitable for your application or fit for any particular purpose, or will operate in" at 160.757,-21.099 h1.14
  text ".Layer_Name" at 14.656,-21.806 h1.52
  text "ALTIUM DESIGNER VERSION:" at 326.352,-23.457 h1.14
  text "an implementation. TI and/or its licensors do not warrant that the design is production worthy. You should" at 160.757,-23.961 h1.14
  text "completely validate and test your design implementation to confirm the system functionality for your application." at 161.9,-26.822 h1.14
  text ".print_Scale" at 289.395,-26.843 h1.78
  text ".Application_BuildNumber" at 327.635,-26.843 h1.78
  text "1" at 18.792,-32.093 h1.78
  text "2" at 82.182,-32.093 h1.78
  text "3" at 145.411,-32.093 h1.78
  text "4" at 209.08,-32.093 h1.78
  text "5" at 272.555,-32.093 h1.78
  text "6" at 336.182,-32.093 h1.78
M10 Fab Notes:
  drawing of 189 lines, arcs and shapes, not listed
  text "DESIGN INFORMATION" at 314.478,153.111 h1.52
  text "MIN. TRACK WIDTH:" at 298.106,148.539 h1.52
  text "8" at 325.951,148.539 h1.52
  text "MIL" at 329.881,148.539 h1.52
  text "MIN. CLEARANCE:" at 298.106,145.186 h1.52
  text "0.2" at 324.427,145.186 h1.52
  text "mm" at 329.881,145.186 h1.52
  text "MIN. VIA PAD SIZE:" at 298.106,141.834 h1.52
  text "24" at 325.189,141.834 h1.52
  text "MIL" at 329.881,141.834 h1.52
  text "0.05mm (2MIL)" at 315.759,138.234 h1.52
  text "MINIMUM ANNULAR RING" at 289.744,138.125 h1.52
  text "EXTERNAL" at 333.742,138.125 h1.52
  text "PER" at 294.824,135.128 h1.52
  text "IPC-D-275 CLASS 2 LEVEL C" at 300.412,135.128 h1.52
  text "MIL, HOLES" at 338.213,132.276 h1.52
  text "+/-" at 328.244,132.258 h1.52
  text "+/-" at 349.936,132.258 h1.52
  text "REGISTRATION TOLERANCES:" at 289.744,132.131 h1.52
  text "METAL" at 320.218,132.131 h1.52
  text "5" at 334.853,132.131 h1.52
  text "3" at 356.012,132.131 h1.52
  text "MIL" at 358.964,132.131 h1.52
  text "+/-" at 349.936,129.261 h1.52
  text "HOLE SIZE TOLERANCE (UNLESS OTHERWISE SPECIFIED):" at 289.744,129.134 h1.52
  text "3" at 356.012,129.134 h1.52
  text "MIL" at 358.964,129.134 h1.52
  text "MATERIAL:" at 287.844,123.813 h1.52
  text "FR-4 High Tg" at 312.9,120.249 h1.52
  text "FR-408" at 298.538,120.031 h1.52
  text "OTHER" at 336.333,120.031 h1.52
  text "X" at 308.966,119.939 h1.52
  text "62 MIL (1.6mm) +/-10%" at 306.668,115.898 h1.52
  text "THICKNESS:" at 289.744,115.789 h1.52
  text "X" at 303.413,115.789 h1.52
  text "OTHER" at 339.305,115.789 h1.52
  text "TOLERANCE:" at 289.744,111.776 h1.52
  text "X" at 311.062,111.776 h1.52
  text "ANSI IPC-6012 TYPE 3 CLASS 2" at 315.81,111.776 h1.52
  text "OTHER +/-" at 315.81,107.814 h1.52
  text "BOW & TWIST:" at 289.744,103.826 h1.52
  text "X" at 311.062,103.826 h1.52
  text "ANSI IPC-6012 TYPE 3 CLASS 2" at 315.81,103.826 h1.52
  text "OTHER +/-" at 315.81,99.8 h1.52
  text "DRILLING:" at 287.844,96.282 h1.52
  text "REFERENCE:" at 289.744,93.31 h1.52
  text "X" at 306.209,93.31 h1.52
  text "AS SHOWN" at 310.958,93.31 h1.52
  text "X" at 329.094,93.31 h1.52
  text "NC_DRILL FILES" at 332.574,93.31 h1.52
  text "PTH MIN COPPER THICKNESS:" at 289.744,89.297 h1.52
  text "X" at 324.039,89.297 h1.52
  text "1MIL" at 327.519,89.297 h1.52
  text "OTHER" at 340.143,89.297 h1.52
  text "BOARD FINISH:" at 287.844,85.259 h1.52
  text "SILKSCREEN:" at 291.787,82.261 h1.52
  text "X" at 315.886,82.261 h1.52
  text "TOP" at 319.086,82.261 h1.52
  text "X" at 328.84,82.261 h1.52
  text "BOTTOM" at 332.066,82.261 h1.52
  text "SILKSCREEN COLOR:" at 291.787,78.02 h1.52
  text "X" at 315.86,78.02 h1.52
  text "WHITE" at 319.086,78.02 h1.52
  text "OTHER" at 332.066,78.02 h1.52
  text "X" at 319.187,73.976 h1.52
  text "GREEN" at 322.414,73.976 h1.52
  text "OTHER" at 338.111,73.976 h1.52
  text "SOLDER RESIST COLOR:" at 291.787,73.702 h1.52
  text "X" at 319.187,69.658 h1.52
  text "MATTE" at 322.414,69.658 h1.52
  text "SEMI-GLOSS" at 338.099,69.642 h1.52
  text "IMMERSION GOLD (ENIG)" at 314.794,64.87 h1.52
  text "ENEPIG" at 348.767,64.786 h1.52
  text "SURFACE FINISH:" at 287.844,64.761 h1.52
  text "X" at 310.045,64.761 h1.52
  text "IMM. TIN/SILVER OR EQUIV" at 296.215,60.773 h1.52
  text "OTHER" at 332.574,60.773 h1.52
  text "ARRAY/PANEL:" at 287.844,56.226 h1.52
  text "CUT AND TRIM PER M1 BOARD OUTLINE" at 314.794,56.118 h1.52
  text "N.C. ROUTE" at 314.794,52.264 h1.52
  text "X" at 332.04,52.264 h1.52
  text "V. SCORE" at 336.79,52.264 h1.52
  text "CERTIFICATION:" at 287.844,48.784 h1.52
  text "MATERIALS AND WORKMANSHIP FOR ALL PCBS" at 306.259,48.784 h1.52
  text "TO MEET OR EXCEED THE REQUIREMENTS OF:" at 306.259,46.295 h1.52
  text "X" at 296.773,42.828 h1.52
  text "ANSI IPC-A-600F CLASS ->" at 300.303,42.828 h1.52
  text "X" at 341.935,42.828 h1.52
  text "2" at 344.956,42.828 h1.52
  text "1" at 336.955,42.79 h1.52
  text "3" at 353.948,42.79 h1.52
  text "X" at 296.825,38.777 h1.52
  text "UL 94V-0" at 300.303,38.777 h1.52
  text "X" at 317.45,38.777 h1.52
  text "RoHS" at 320.928,38.777 h1.52
  text "OTHER" at 337.296,38.777 h1.52
  text "PER ORDER" at 347.381,38.777 h1.52
  text "ADDITIONAL REQUIREMENTS:" at 287.844,35.195 h1.52
  text "MICROSECTION:" at 289.744,32.274 h1.52
  text "YES" at 312.749,32.274 h1.52
  text "REQUIRED" at 334.631,28.308 h1.52
  text "BARE BOARD ELEC. TEST:" at 289.744,28.236 h1.52
  text "NONE" at 322.909,28.236 h1.52
  text "X" at 331.405,28.236 h1.52
  text "PER ORDER" at 349.668,28.236 h1.52
  text "MANUFACTURER'S UL:" at 289.744,24.248 h1.52
  text "RAIL" at 319.353,24.139 h1.52
  text "METAL" at 331.845,24.139 h1.52
  text "X" at 341.376,24.13 h1.52
  text "SILK" at 344.842,24.139 h1.52
  text ".Layer_Name" at 14.656,-21.806 h1.52
M11 Gerber Information:
  lines w0.254: -7.417,-23.626 160.223,-23.626 ; -7.417,-18.462 160.274,-18.462 ; -7.417,-13.297 -7.417,-28.791 94.31,-28.791 160.274,-28.791 160.274,-13.297 -7.404,-13.297 -7.404,-28.791 32.614,-28.791 ; 55.194,-28.791 55.194,-13.297 ; 87.376,-18.462 87.376,-13.297 ; 108.712,-18.462 108.712,-13.297 ; 124.511,-28.956 124.511,-23.804
  text "ALL ARTWORK VIEWED FROM TOP SIDE" at -5.804,-16.654 h1.52
  text "BOARD #:" at 57.099,-16.654 h1.52
  text ".PRJ_Number" at 70.955,-16.654 h1.52
  text "REV:" at 92.405,-16.654 h1.52
  text ".PCB_Rev" at 99.809,-16.654 h1.52
  text "SVN REV:" at 113.69,-16.654 h1.52
  text ".VersionControl_RevNumber" at 126.543,-16.654 h1.52
  text "LAYER NAME =" at -5.804,-21.806 h1.52
  text "TID #:" at 57.099,-21.819 h1.52
  text ".TID" at 70.955,-21.819 h1.52
  text "PLOT NAME =" at -5.804,-27.034 h1.52
  text ".plot_File_Name" at 14.656,-27.034 h1.52
  text "GENERATED    :" at 57.15,-27.034 h1.52
  text ".Print_Date" at 79.235,-27.034 h1.52
  text ".Print_Time" at 97.752,-27.034 h1.52
  text "TEXAS INSTRUMENTS" at 129.87,-27.034 h1.52
M12 Stackup:
  text ".Layer_Name" at 14.656,-21.806 h1.52
M13 Component Bodies Top:
  text ".Layer_Name" at 14.656,-21.806 h1.52
M14 Component Bodies Bottom:
  text ".Layer_Name" at 14.656,-21.806 h1.52
M15 Courtyards Top:
  text ".Layer_Name" at 14.656,-21.806 h1.52
M16 Courtyards Bottom:
  text ".Layer_Name" at 14.656,-21.806 h1.52
Drill Drawing:
  lines w0.025: 38.807,6.662 39.123,6.662 39.439,6.346 39.755,6.662 40.071,6.662 39.755,6.978 40.071,7.294 39.755,7.294 39.439,7.61 39.123,7.294 38.807,7.294 39.123,6.978 38.807,6.662 ; 38.807,10.455 39.123,10.455 39.123,10.139 39.755,10.139 39.755,10.455 40.071,10.455 40.071,11.087 39.755,11.087 39.755,11.403 39.123,11.403 39.123,11.087 38.807,11.087 38.807,10.455
  lines w0.305: 37.084,5.208 90.882,5.208 ; 37.084,12.793 90.882,12.793 ; 46.491,1.415 46.491,16.586 ; 55.559,1.415 55.559,16.586 ; 72.363,1.415 72.363,16.586 ; 79.58,1.415 79.58,16.586 ; 37.084,1.415 90.882,1.415 90.882,16.586 37.084,16.586 37.084,1.415
  text "Symbol" at 39.36,13.931 h1.83
  text "Quantity" at 47.629,13.931 h1.83
  text "Finished Hole Size" at 56.697,13.931 h1.83
  text "Plated" at 73.501,13.931 h1.83
  text "Hole Type" at 80.718,13.931 h1.83
  text "13" at 47.629,10.139 h1.52
  text "0.300mm (11.81mil)" at 56.697,10.139 h1.52
  text "PTH" at 73.501,10.139 h1.52
  text "Round" at 80.718,10.139 h1.52
  text "7" at 47.629,6.346 h1.52
  text "1.150mm (45.28mil)" at 56.697,6.346 h1.52
  text "PTH" at 73.501,6.346 h1.52
  text "Round" at 80.718,6.346 h1.52
  text "20 Total" at 47.629,2.553 h1.52
  text ".Layer_Name" at 14.656,-21.806 h1.52

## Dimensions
0,-10.16 to 25.4,-10.16 on M2 Board Dimensions
0,0 to 0,22.86 on M2 Board Dimensions
0,0 to 22.86,0 on M2 Board Dimensions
